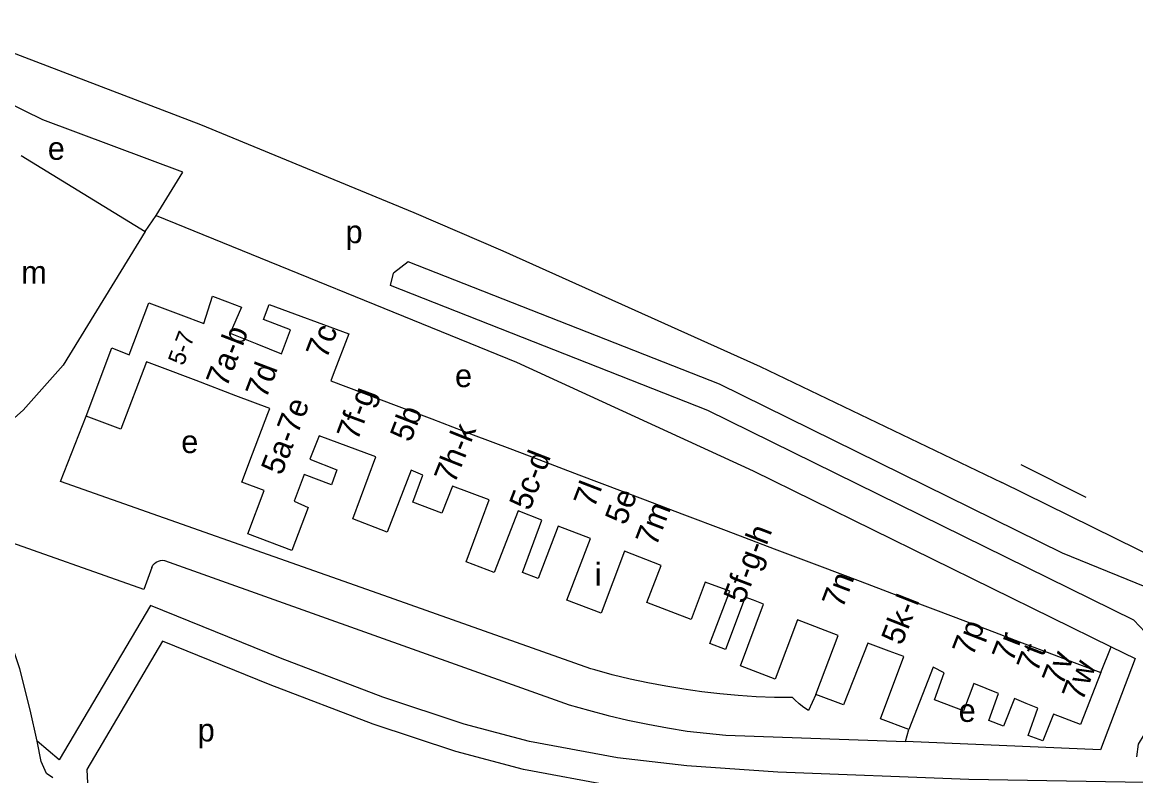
# Model space of a CAD drawing. Extents: x 163012 to 165277, y 382513 to 383987.
# Drawn here: x 163855 to 164049.6, y 383703.3 to 383835.1 of the extents above; entities that cross this region are included whole.
import ezdxf

# ---------------------------------------------------------------- set-up
doc = ezdxf.new("R2010")
doc.units = 0
for name, color, linetype in [('BLT_Basislijn', 7, 'Continuous'), ('BLT_Bebouwing', 7, 'Continuous'), ('BLT_Centroide', 7, 'Continuous'), ('BLT_Huisnummer_reeks', 7, 'Continuous'), ('BLT_Spoorlijn', 7, 'Continuous')]:
    doc.layers.add(name, color=color, linetype=linetype)

msp = doc.modelspace()

# ---------------------------------------------------------------- linework, layer by layer
at = {"layer": 'BLT_Basislijn'}
for p, q in [((163839.35, 383835.06), (163886.12, 383817.2)), ((163886.12, 383817.2), (163923.4, 383801.76)), ((163923.4, 383801.76), (163938.95, 383795.08)), ((163876.46, 383798.46), (163878.37, 383801.23)), ((163938.95, 383795.08), (163983.91, 383774.84)), ((163983.91, 383774.84), (164026.2, 383754.53)), ((164036.76, 383742.2), (163976.82, 383771.74)), ((164049.23, 383730.48), (163974.79, 383767.16)), ((164057.41, 383739.12), (164026.2, 383754.53)), ((163879.83, 383740.92), (163950.55, 383715.67)), ((164043.45, 383721.33), (164045.31, 383725.81)), ((163993.65, 383717.49), (163992.38, 383714.66)), ((164009.35, 383709.23), (164009.91, 383711.32))]:
    msp.add_line(p, q, dxfattribs=at)
for points in [[(163878.37, 383801.23), (163883.03, 383808.82), (163858.57, 383817.98), (163852.05, 383821.17)], [(163878.37, 383801.23), (163941.34, 383775.62), (163982.71, 383756.59), (164045.31, 383725.81)], [(163976.82, 383771.74), (163922.44, 383793.14), (163919.87, 383791.18)], [(163974.79, 383767.16), (163919.31, 383789), (163919.87, 383791.18)], [(163954.34, 383721.97), (163917.2, 383735.14), (163861.65, 383754.72), (163866.17, 383766.16)], [(163877.6, 383739.71), (163876.21, 383735.83), (163850.12, 383745.06)], [(164128.33, 383695.88), (164126.27, 383697.13), (164073.56, 383727.23), (164036.76, 383742.2)], [(163877.6, 383739.71), (163877.8, 383740.07), (163878.07, 383740.37), (163878.4, 383740.62), (163878.76, 383740.8), (163879.16, 383740.91), (163879.57, 383740.94), (163879.83, 383740.92)], [(164054.55, 383702.03), (164020.4, 383702.59), (163987.05, 383703.91), (163971.11, 383704.98), (163958.98, 383706.41), (163943.65, 383709.26), (163932.2, 383712.28), (163917.98, 383717), (163900.12, 383723.82), (163877.39, 383733.06), (163861.41, 383706.02), (163857.55, 383709.28)], [(164049.23, 383730.48), (164055.16, 383724.2), (164056.6, 383720.91), (164057.98, 383717.99), (164054.55, 383714.97), (164052.01, 383712.07), (164050, 383708.79), (164049.69, 383706.55)], [(163857.55, 383709.28), (163856.38, 383714.79), (163854.55, 383721.96), (163852.72, 383727.44)], [(164049.11, 383697.12), (164020.26, 383697.6), (163986.78, 383698.92), (163970.65, 383700), (163958.23, 383701.46), (163942.55, 383704.38), (163930.77, 383707.49), (163916.3, 383712.29), (163898.28, 383719.17), (163879.5, 383726.81), (163866.23, 383704.35), (163866.45, 383700.78)], [(164045.31, 383725.81), (164049.46, 383723.77), (164043.4, 383707.77), (164009.35, 383709.23)], [(163989.61, 383716.92), (163986.42, 383716.97), (163983.24, 383717.09), (163980.07, 383717.29), (163976.89, 383717.58), (163973.73, 383717.94), (163970.58, 383718.38), (163967.43, 383718.9), (163964.31, 383719.5), (163961.2, 383720.18), (163958.1, 383720.93), (163955.03, 383721.77), (163954.34, 383721.97)], [(163992.38, 383714.66), (163991.54, 383715.22), (163990.74, 383715.84), (163989.99, 383716.53), (163989.61, 383716.92)], [(163950.55, 383715.67), (163953.96, 383714.71), (163957.38, 383713.82), (163960.82, 383713.01), (163964.28, 383712.28), (163967.76, 383711.63), (163971.16, 383711.07)], [(163971.16, 383711.07), (163977.91, 383710.38), (164009.35, 383709.23)], [(163860.29, 383702.92), (163859.23, 383703.63), (163858.28, 383705.77), (163857.55, 383709.28)]]:
    msp.add_lwpolyline(points, dxfattribs=at)
at = {"layer": 'BLT_Bebouwing'}
for p, q in [((163854.78, 383811.77), (163876.46, 383798.46)), ((163895.95, 383778.81), (163900.26, 383777.07)), ((163885.34, 383772.37), (163879.01, 383774.77)), ((163892.31, 383769.73), (163885.34, 383772.37)), ((163909.33, 383773.44), (163908.92, 383772.36)), ((163908.92, 383772.36), (163920.34, 383768.03)), ((163895.21, 383759.57), (163897.89, 383766.63)), ((163920.34, 383768.03), (163926.55, 383765.67)), ((163926.55, 383765.67), (163933.8, 383762.92)), ((163933.8, 383762.92), (163940.19, 383760.5)), ((163940.19, 383760.5), (163945.24, 383758.58)), ((163945.24, 383758.58), (163952.25, 383755.92)), ((163952.25, 383755.92), (163963.85, 383751.52)), ((163936.6, 383751.52), (163930.18, 383753.89)), ((163963.85, 383751.52), (163970.23, 383749.1)), ((163970.23, 383749.1), (163977.97, 383746.17)), ((163977.97, 383746.17), (163986.4, 383742.97)), ((163986.4, 383742.97), (163994.3, 383739.97)), ((163966.61, 383740.06), (163960.25, 383742.52)), ((163994.3, 383739.97), (164001.42, 383737.27)), ((164001.42, 383737.27), (164010.07, 383733.99)), ((164010.07, 383733.99), (164017.68, 383731.1)), ((163997.58, 383727.8), (163990.47, 383730.51)), ((164017.68, 383731.1), (164024.9, 383728.36)), ((163993.65, 383717.49), (163997.58, 383727.8)), ((164024.9, 383728.36), (164029.26, 383726.71)), ((164029.26, 383726.71), (164034.1, 383724.88)), ((164034.1, 383724.88), (164038.8, 383723.09)), ((164014.15, 383722.27), (164009.91, 383711.32)), ((164038.8, 383723.09), (164043.45, 383721.33)), ((164025.61, 383717.62), (164021.3, 383719.37))]:
    msp.add_line(p, q, dxfattribs=at)
for points in [[(163876.46, 383798.46), (163862.1, 383775.1), (163855.16, 383767.19), (163849.4, 383762.22)], [(163866.17, 383766.16), (163870.65, 383778.08), (163873.68, 383776.9), (163877.11, 383785.96), (163882.66, 383783.87)], [(163882.66, 383783.87), (163886.68, 383782.35), (163888.2, 383787.15), (163890.86, 383786.15)], [(163890.86, 383786.15), (163893.29, 383785.22), (163891.32, 383780.68), (163895.95, 383778.81)], [(163900.26, 383777.07), (163901.84, 383781.24), (163897.16, 383783.09), (163898.15, 383785.66)], [(163898.15, 383785.66), (163912.03, 383780.56), (163909.33, 383773.44)], [(163879.01, 383774.77), (163876.67, 383775.65), (163872.21, 383763.87), (163866.17, 383766.16)], [(163897.89, 383766.63), (163898.22, 383767.5), (163892.31, 383769.73)], [(163906.84, 383762.7), (163905.25, 383758.61), (163909.98, 383756.75), (163909, 383754.17), (163904.26, 383755.95)], [(163916.74, 383759.03), (163906.84, 383762.7)], [(163904.26, 383755.95), (163902.5, 383751.26), (163904.94, 383750.17), (163902.07, 383742.65), (163894.39, 383745.57), (163897.27, 383753.17), (163893.33, 383754.62), (163895.21, 383759.57)], [(163922.97, 383756.74), (163918.74, 383745.88), (163912.73, 383748.18), (163916.74, 383759.03)], [(163930.18, 383753.89), (163928.31, 383749.18), (163923.23, 383751.1), (163924.97, 383755.82), (163922.97, 383756.74)], [(163941.66, 383749.62), (163937.45, 383738.79), (163932.55, 383740.65), (163936.6, 383751.52)], [(163948.65, 383746.93), (163945.11, 383737.78), (163942.39, 383738.82), (163945.78, 383747.98), (163941.66, 383749.62)], [(163960.25, 383742.52), (163956.15, 383731.72), (163950.13, 383734), (163954.29, 383744.78), (163948.65, 383746.93)], [(163974.34, 383737.11), (163971.88, 383730.61), (163964.12, 383733.54), (163966.61, 383740.06)], [(163982.8, 383733.95), (163981.33, 383734.51), (163977.86, 383725.35), (163975.12, 383726.4), (163978.65, 383735.57), (163974.34, 383737.11)], [(163990.47, 383730.51), (163986.55, 383720.18), (163980.51, 383722.48), (163984.54, 383733.29), (163982.8, 383733.95)], [(164006.49, 383725.06), (164002.75, 383726.47), (163998.5, 383715.64), (163993.65, 383717.49)], [(164009.91, 383711.32), (164004.95, 383713.2), (164009.02, 383724.11), (164006.49, 383725.06)], [(164021.3, 383719.37), (164019.46, 383714.62), (164014.4, 383716.53), (164016.12, 383721.25), (164014.15, 383722.27)], [(164043.45, 383721.33), (164039.95, 383712.22), (164035.18, 383714.05)], [(164030.41, 383715.91), (164028.36, 383716.75), (164026.47, 383711.95), (164023.89, 383712.94), (164025.61, 383717.62)], [(164035.18, 383714.05), (164033.32, 383709.35), (164030.76, 383710.32), (164032.45, 383715.06), (164030.41, 383715.91)]]:
    msp.add_lwpolyline(points, dxfattribs=at)
at = {"layer": 'BLT_Spoorlijn'}
msp.add_lwpolyline([(164029.48, 383757.71), (164040.87, 383752.01)], dxfattribs=at)

# ---------------------------------------------------------------- texts
at = {"layer": 'BLT_Centroide'}
for s, p in [('e', (163859.44, 383811)), ('p', (163911.48, 383796.42)), ('m', (163854.81, 383789.33)), ('e', (163930.61, 383771.24)), ('e', (163882.76, 383759.7)), ('i', (163955.03, 383736.48)), ('e', (164018.63, 383712.68)), ('p', (163885.64, 383709.26))]:
    msp.add_text(s, height=4, dxfattribs=at).set_placement(p)
at = {"layer": 'BLT_Huisnummer_reeks'}
for s, height, rotation, p in [('7c', 4, 69.2202, (163908.15, 383775.98)), ('5-7', 3, 69.2731, (163883.14, 383774.85)), ('7a-b', 4, 68.7955, (163890.68, 383771.01)), ('7d', 4, 69.2182, (163897.58, 383769.02)), ('7f-g', 4, 69.7294, (163913.55, 383761.67)), ('5a-7e', 4, 68.7955, (163900.29, 383755.63)), ('5b', 4, 68.7184, (163922.82, 383761.43)), ('7h-k', 4, 68.3476, (163930.53, 383754.16)), ('5c-d', 4, 68.7278, (163943.65, 383749.45)), ('7l', 4, 68.9098, (163954.91, 383749.89)), ('5e', 4, 69.2349, (163960.42, 383746.93)), ('7m', 4, 69.151, (163965.76, 383743.2)), ('5f-g-h', 4, 68.983, (163981.1, 383733.16)), ('7n', 4, 69.1576, (163998.33, 383732.33)), ('5k-l', 4, 68.5701, (164008.68, 383725.89)), ('7p', 4, 68.8511, (164021.09, 383723.96)), ('7r', 4, 68.471, (164028.02, 383722.95)), ('7t', 4, 68.8511, (164032.34, 383721.15)), ('7v', 4, 68.471, (164036.76, 383718.82)), ('7w', 4, 68.9878, (164040.26, 383716.11))]:
    msp.add_text(s, height=height, rotation=rotation, dxfattribs=at).set_placement(p)

doc.saveas('drawing.dxf')
